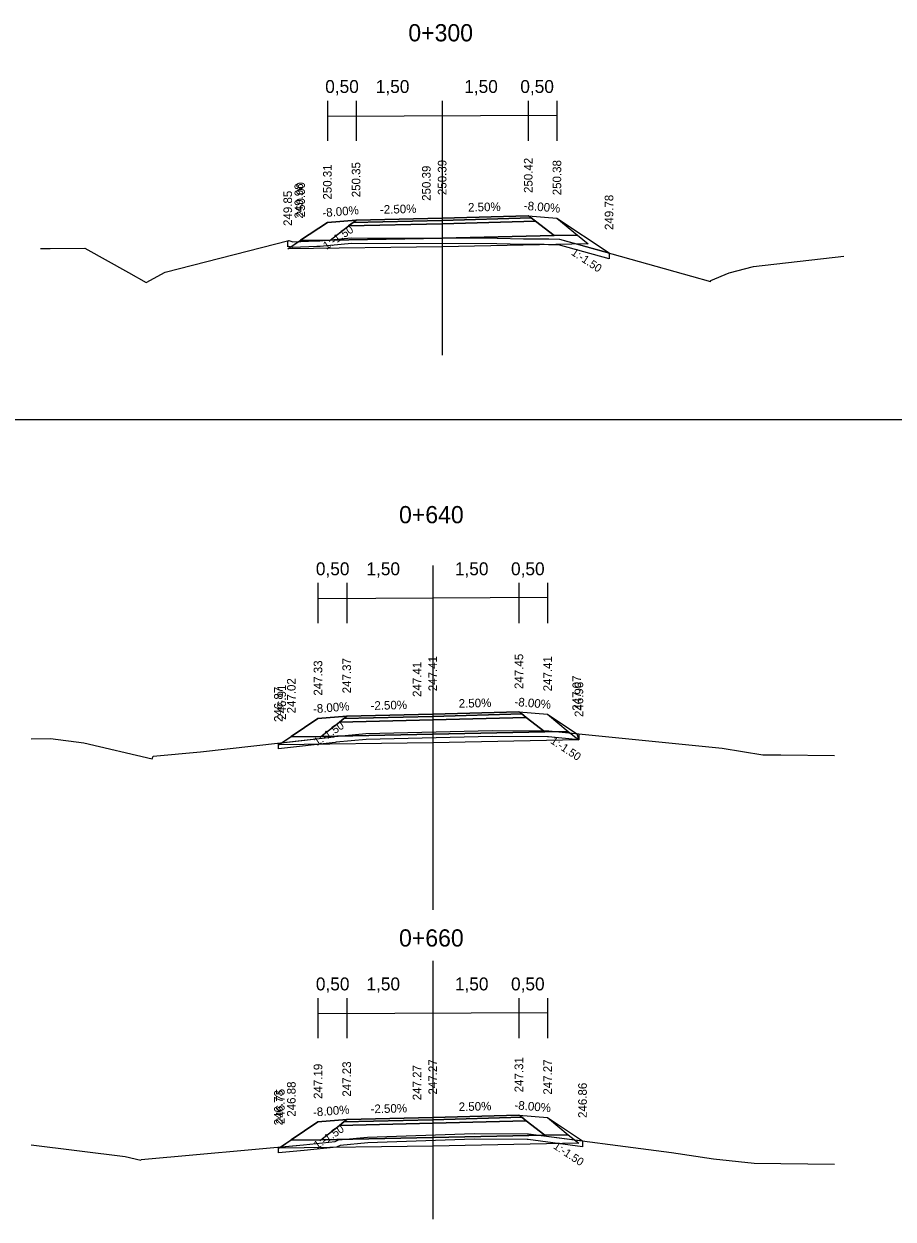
# Model space of a CAD drawing. Extents: x -552501 to -552394, y -1029983 to -1029892.
# Drawn here: x -552453.26 to -552438.12, y -1029936.98 to -1029916.15 of the extents above; entities that cross this region are included whole.
import ezdxf

# ---------------------------------------------------------------- set-up
doc = ezdxf.new("R2010")
doc.units = 0
for name, color, linetype in [('1', 7, 'Continuous'), ('16', 7, 'Continuous'), ('60', 7, 'Continuous'), ('9', 7, 'Continuous'), ('Implicitní', 7, 'Continuous'), ('rámeček', 7, 'Continuous')]:
    doc.layers.add(name, color=color, linetype=linetype)

msp = doc.modelspace()

# ---------------------------------------------------------------- linework, layer by layer
for points in [[(-552448.667, -1029920.075), (-552448.474, -1029919.946), (-552448.442, -1029919.925), (-552447.977, -1029919.615), (-552447.477, -1029919.575), (-552445.977, -1029919.537), (-552444.477, -1029919.5), (-552443.977, -1029919.54), (-552443.069, -1029920.145)], [(-552452.977, -1029920.066), (-552452.808, -1029920.066), (-552452.203, -1029920.059), (-552451.441, -1029920.486), (-552451.136, -1029920.663), (-552450.803, -1029920.482), (-552448.646, -1029919.931), (-552448.576, -1029919.95), (-552448.164, -1029919.935), (-552448.108, -1029919.933), (-552447.561, -1029919.879), (-552445.02, -1029919.887), (-552444.56, -1029919.898), (-552444.198, -1029919.898), (-552444.12, -1029919.901), (-552443.933, -1029919.903), (-552441.634, -1029920.548), (-552441.301, -1029920.644), (-552441.293, -1029920.624), (-552440.976, -1029920.489), (-552440.553, -1029920.383), (-552438.977, -1029920.203)], [(-552448.83, -1029928.72), (-552448.772, -1029928.682), (-552448.605, -1029928.57), (-552448.14, -1029928.26), (-552447.64, -1029928.22), (-552446.14, -1029928.183), (-552444.64, -1029928.145), (-552444.14, -1029928.185), (-552443.632, -1029928.524), (-552443.594, -1029928.633)], [(-552453.14, -1029928.611), (-552452.803, -1029928.608), (-552452.222, -1029928.681), (-552451.031, -1029928.96), (-552451.01, -1029928.913), (-552450.189, -1029928.839), (-552447.864, -1029928.581), (-552447.846, -1029928.573), (-552447.308, -1029928.522), (-552445.107, -1029928.47), (-552444.144, -1029928.476), (-552444.118, -1029928.476), (-552441.097, -1029928.775), (-552440.387, -1029928.891), (-552440.075, -1029928.891), (-552439.14, -1029928.903)], [(-552448.83, -1029935.749), (-552448.796, -1029935.727), (-552448.605, -1029935.599), (-552448.14, -1029935.289), (-552447.64, -1029935.249), (-552446.14, -1029935.212), (-552444.64, -1029935.174), (-552444.14, -1029935.214), (-552443.531, -1029935.62)], [(-552453.14, -1029935.689), (-552451.501, -1029935.893), (-552451.227, -1029935.957), (-552451.223, -1029935.946), (-552448.393, -1029935.691), (-552447.843, -1029935.63), (-552447.78, -1029935.603), (-552447.28, -1029935.555), (-552445.418, -1029935.491), (-552444.493, -1029935.497), (-552444.473, -1029935.497), (-552441.979, -1029935.824), (-552441.248, -1029935.933), (-552440.542, -1029936.011), (-552439.14, -1029936.024)]]:
    msp.add_lwpolyline(points)
for points in [[(-552445.978, -1029919.577), (-552447.528, -1029919.615), (-552447.606, -1029919.675), (-552445.978, -1029919.637), (-552444.349, -1029919.594), (-552444.426, -1029919.534), (-552445.978, -1029919.577), (-552444.426, -1029919.534), (-552444.477, -1029919.5), (-552445.977, -1029919.537), (-552447.477, -1029919.575), (-552447.528, -1029919.615)], [(-552447.606, -1029919.675), (-552447.528, -1029919.615), (-552445.978, -1029919.577), (-552444.426, -1029919.534), (-552444.349, -1029919.594), (-552445.978, -1029919.637)], [(-552444.477, -1029919.5), (-552443.977, -1029919.54), (-552443.616, -1029919.837), (-552444.027, -1029919.844), (-552444.349, -1029919.594), (-552444.426, -1029919.534)], [(-552447.477, -1029919.575), (-552447.977, -1029919.615), (-552448.442, -1029919.925), (-552447.928, -1029919.925)], [(-552447.928, -1029919.925), (-552447.606, -1029919.675), (-552445.978, -1029919.637), (-552444.349, -1029919.594), (-552444.027, -1029919.844), (-552445.978, -1029919.887)], [(-552448.667, -1029920.075), (-552448.442, -1029919.925), (-552447.928, -1029919.925), (-552445.978, -1029919.887), (-552444.027, -1029919.844), (-552443.616, -1029919.837), (-552443.431, -1029919.987), (-552445.978, -1029920.037)], [(-552448.667, -1029919.937), (-552448.646, -1029919.931), (-552448.576, -1029919.95), (-552448.164, -1029919.935), (-552448.108, -1029919.933), (-552447.561, -1029919.879), (-552445.02, -1029919.887), (-552444.56, -1029919.898), (-552444.198, -1029919.898), (-552444.12, -1029919.901), (-552443.933, -1029919.903), (-552443.069, -1029920.145), (-552443.069, -1029920.249), (-552443.947, -1029920.003), (-552444.122, -1029920.001), (-552444.2, -1029919.998), (-552444.561, -1029919.998), (-552445.022, -1029919.987), (-552447.556, -1029919.979), (-552448.101, -1029920.033), (-552448.161, -1029920.035), (-552448.587, -1029920.05), (-552448.646, -1029920.035), (-552448.667, -1029920.04)], [(-552447.64, -1029928.22), (-552448.14, -1029928.26), (-552448.605, -1029928.57), (-552448.09, -1029928.57)], [(-552448.09, -1029928.57), (-552447.768, -1029928.32), (-552446.14, -1029928.283), (-552444.512, -1029928.239), (-552444.19, -1029928.489), (-552446.14, -1029928.533)], [(-552446.14, -1029928.223), (-552447.691, -1029928.26), (-552447.768, -1029928.32), (-552446.14, -1029928.283), (-552444.512, -1029928.239), (-552444.589, -1029928.179), (-552446.14, -1029928.223), (-552444.589, -1029928.179), (-552444.64, -1029928.145), (-552446.14, -1029928.183), (-552447.64, -1029928.22), (-552447.691, -1029928.26)], [(-552447.768, -1029928.32), (-552447.691, -1029928.26), (-552446.14, -1029928.223), (-552444.589, -1029928.179), (-552444.512, -1029928.239), (-552446.14, -1029928.283)], [(-552444.64, -1029928.145), (-552444.14, -1029928.185), (-552443.779, -1029928.483), (-552444.19, -1029928.489), (-552444.512, -1029928.239), (-552444.589, -1029928.179)], [(-552448.83, -1029928.688), (-552447.864, -1029928.581), (-552447.846, -1029928.573), (-552447.308, -1029928.522), (-552445.107, -1029928.47), (-552444.144, -1029928.476), (-552444.118, -1029928.476), (-552443.594, -1029928.528), (-552443.594, -1029928.628), (-552444.123, -1029928.576), (-552444.144, -1029928.576), (-552445.106, -1029928.57), (-552447.302, -1029928.622), (-552447.821, -1029928.671), (-552447.839, -1029928.679), (-552448.83, -1029928.789)], [(-552448.83, -1029928.72), (-552448.605, -1029928.57), (-552448.09, -1029928.57), (-552446.14, -1029928.533), (-552444.19, -1029928.489), (-552443.779, -1029928.483), (-552443.594, -1029928.633), (-552446.14, -1029928.683)], [(-552446.14, -1029935.252), (-552447.691, -1029935.289), (-552447.768, -1029935.349), (-552446.14, -1029935.312), (-552444.512, -1029935.268), (-552444.589, -1029935.208), (-552446.14, -1029935.252), (-552444.589, -1029935.208), (-552444.64, -1029935.174), (-552446.14, -1029935.212), (-552447.64, -1029935.249), (-552447.691, -1029935.289)], [(-552444.64, -1029935.174), (-552444.14, -1029935.214), (-552443.779, -1029935.512), (-552444.19, -1029935.518), (-552444.512, -1029935.268), (-552444.589, -1029935.208)], [(-552447.64, -1029935.249), (-552448.14, -1029935.289), (-552448.605, -1029935.599), (-552448.09, -1029935.599)], [(-552448.09, -1029935.599), (-552447.768, -1029935.349), (-552446.14, -1029935.312), (-552444.512, -1029935.268), (-552444.19, -1029935.518), (-552446.14, -1029935.562)], [(-552447.768, -1029935.349), (-552447.691, -1029935.289), (-552446.14, -1029935.252), (-552444.589, -1029935.208), (-552444.512, -1029935.268), (-552446.14, -1029935.312)], [(-552448.83, -1029935.73), (-552448.393, -1029935.691), (-552447.843, -1029935.63), (-552447.78, -1029935.603), (-552447.28, -1029935.555), (-552445.418, -1029935.491), (-552444.493, -1029935.497), (-552444.473, -1029935.497), (-552443.531, -1029935.62), (-552443.531, -1029935.721), (-552444.48, -1029935.597), (-552444.493, -1029935.597), (-552445.417, -1029935.591), (-552447.274, -1029935.655), (-552447.755, -1029935.701), (-552447.818, -1029935.728), (-552448.383, -1029935.79), (-552448.83, -1029935.831)], [(-552448.83, -1029935.749), (-552448.605, -1029935.599), (-552448.09, -1029935.599), (-552446.14, -1029935.562), (-552444.19, -1029935.518), (-552443.779, -1029935.512), (-552443.594, -1029935.662), (-552446.14, -1029935.712)]]:
    msp.add_lwpolyline(points, close=True)
at = {"layer": '60'}
for p, q in [((-552445.977, -1029917.924), (-552445.977, -1029921.924)), ((-552446.14, -1029925.593), (-552446.14, -1029931.593)), ((-552446.14, -1029932.48), (-552446.14, -1029936.983))]:
    msp.add_line(p, q, dxfattribs=at)
at = {"layer": '9'}
for p, q in [((-552447.977, -1029917.492), (-552447.977, -1029918.19)), ((-552447.477, -1029917.492), (-552447.477, -1029918.19)), ((-552445.977, -1029917.492), (-552445.977, -1029918.992)), ((-552444.477, -1029917.492), (-552444.477, -1029918.19)), ((-552443.977, -1029917.492), (-552443.977, -1029918.19)), ((-552448.14, -1029925.897), (-552448.14, -1029926.595)), ((-552447.64, -1029925.897), (-552447.64, -1029926.595)), ((-552446.14, -1029925.897), (-552446.14, -1029927.397)), ((-552444.64, -1029925.897), (-552444.64, -1029926.595)), ((-552444.14, -1029925.897), (-552444.14, -1029926.595)), ((-552448.14, -1029933.132), (-552448.14, -1029933.829)), ((-552447.64, -1029933.132), (-552447.64, -1029933.829)), ((-552446.14, -1029933.132), (-552446.14, -1029934.632)), ((-552444.64, -1029933.132), (-552444.64, -1029933.829)), ((-552444.14, -1029933.132), (-552444.14, -1029933.829))]:
    msp.add_line(p, q, dxfattribs=at)
at = {"layer": 'Implicitní'}
for p, q in [((-552447.967, -1029917.76), (-552443.977, -1029917.742)), ((-552448.13, -1029926.165), (-552444.14, -1029926.147)), ((-552448.13, -1029933.399), (-552444.14, -1029933.382))]:
    msp.add_line(p, q, dxfattribs=at)
at = {"layer": 'rámeček'}
msp.add_line((-552499.755, -1029923.05), (-552394.755, -1029923.05), dxfattribs=at)
msp.add_line((-552499.755, -1029923.05), (-552394.755, -1029923.05), dxfattribs=at)
msp.add_line((-552499.755, -1029923.05), (-552394.755, -1029923.05), dxfattribs=at)

# ---------------------------------------------------------------- texts
for rotation, p in [(33.6902, (-552447.993, -1029920.094)), (326.3098, (-552443.74, -1029920.167)), (33.6902, (-552448.156, -1029928.74)), (326.3098, (-552444.102, -1029928.679)), (33.6902, (-552448.156, -1029935.769)), (326.3098, (-552444.052, -1029935.742))]:
    msp.add_text('1:-1.50', height=0.14, rotation=rotation).set_placement(p)
at = {"layer": '1'}
for s, p in [('0+300', (-552446.566, -1029916.458)), ('0+640', (-552446.728, -1029924.856)), ('0+660', (-552446.728, -1029932.233))]:
    msp.add_text(s, height=0.3, dxfattribs=at).set_placement(p)
at = {"layer": '16'}
for s, p in [('0,50', (-552448.014, -1029917.357)), ('1,50', (-552447.133, -1029917.357)), ('1,50', (-552445.592, -1029917.357)), ('0,50', (-552444.615, -1029917.357)), ('0,50', (-552448.177, -1029925.762)), ('1,50', (-552447.296, -1029925.762)), ('1,50', (-552445.755, -1029925.762)), ('0,50', (-552444.777, -1029925.762)), ('0,50', (-552448.177, -1029932.997)), ('1,50', (-552447.296, -1029932.997)), ('1,50', (-552445.755, -1029932.997)), ('0,50', (-552444.777, -1029932.997))]:
    msp.add_text(s, height=0.225, dxfattribs=at).set_placement(p)
for s, rotation, p in [('250.42', 90, (-552444.402, -1029919.1)), ('250.31', 90, (-552447.902, -1029919.215)), ('250.35', 90, (-552447.402, -1029919.175)), ('250.39', 90, (-552446.177, -1029919.237)), ('250.39', 90, (-552445.902, -1029919.137)), ('250.38', 90, (-552443.902, -1029919.14)), ('249.98', 90, (-552448.399, -1029919.546)), ('250.00', 90, (-552448.367, -1029919.525)), ('249.85', 90, (-552448.592, -1029919.675)), ('249.78', 90, (-552442.994, -1029919.745)), ('-8.00%', 4.5739, (-552448.058, -1029919.521)), ('-2.50%', 1.4321, (-552447.059, -1029919.464)), ('2.50%', 1.4321, (-552445.524, -1029919.426)), ('-8.00%', 355.4261, (-552444.558, -1029919.393)), ('247.33', 90, (-552448.065, -1029927.86)), ('247.37', 90, (-552447.565, -1029927.82)), ('247.41', 90, (-552446.065, -1029927.783)), ('247.45', 90, (-552444.565, -1029927.745)), ('247.41', 90, (-552444.065, -1029927.785)), ('247.41', 90, (-552446.34, -1029927.883)), ('246.91', 90, (-552448.697, -1029928.282)), ('247.02', 90, (-552448.53, -1029928.17)), ('247.07', 90, (-552443.557, -1029928.124)), ('246.96', 90, (-552443.519, -1029928.233)), ('246.87', 90, (-552448.755, -1029928.32)), ('-8.00%', 355.4261, (-552444.721, -1029928.039)), ('-8.00%', 4.5739, (-552448.221, -1029928.167)), ('-2.50%', 1.4321, (-552447.222, -1029928.11)), ('2.50%', 1.4321, (-552445.687, -1029928.072)), ('247.19', 90, (-552448.065, -1029934.889)), ('247.23', 90, (-552447.565, -1029934.849)), ('247.27', 90, (-552446.34, -1029934.912)), ('247.27', 90, (-552446.065, -1029934.812)), ('247.31', 90, (-552444.565, -1029934.774)), ('247.27', 90, (-552444.065, -1029934.814)), ('246.73', 90, (-552448.755, -1029935.349)), ('246.75', 90, (-552448.721, -1029935.327)), ('246.88', 90, (-552448.53, -1029935.199)), ('246.86', 90, (-552443.456, -1029935.22)), ('-2.50%', 1.4321, (-552447.222, -1029935.139)), ('2.50%', 1.4321, (-552445.687, -1029935.101)), ('-8.00%', 355.4261, (-552444.721, -1029935.068)), ('-8.00%', 4.5739, (-552448.221, -1029935.196))]:
    msp.add_text(s, height=0.15, rotation=rotation, dxfattribs=at).set_placement(p)

doc.saveas('drawing.dxf')
